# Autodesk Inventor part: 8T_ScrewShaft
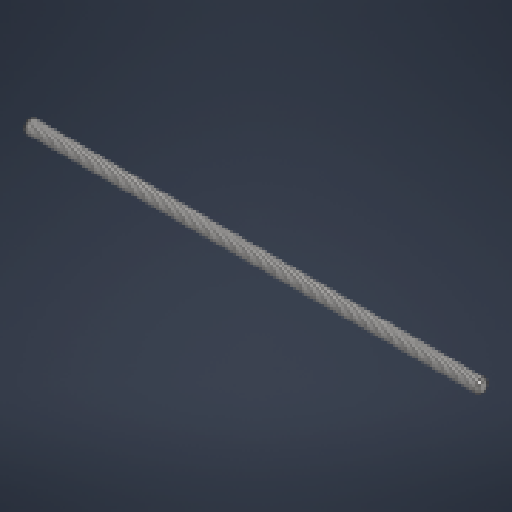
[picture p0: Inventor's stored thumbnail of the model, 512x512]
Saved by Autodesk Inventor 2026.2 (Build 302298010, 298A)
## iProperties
Created: 2025-09
Part Number: 8T_ScrewShaft
Material: 스테인리스스틸
Document SubType Name: Modeling
Designer: work
Density: 8 g/cm^3
Appearance: 반연마
Author: work
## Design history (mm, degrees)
sketch "스케치1"
  geometry: C1 r 4 at (0, 0); 1 further point
  constraints: 1 centre point, 1 coincident
  dimensions: "d0" = 8 diameter of C1
extrude "돌출1" new body sketch "스케치1" distance "d1" = 400; taper "d2" = 0 deg
chamfer "모따기1" distance "d3" = 1; stored, may be unused: second distance "d4" = 2, angle "d5" = 45 deg
feature "스레드1" dims "d6" = 428, "d7" = 0
node "솔리드1"
feature "A9D066F2-1C7D-4E18-AEED-F7BC21143FA4" dims "d6" = 428, "d7" = 0
